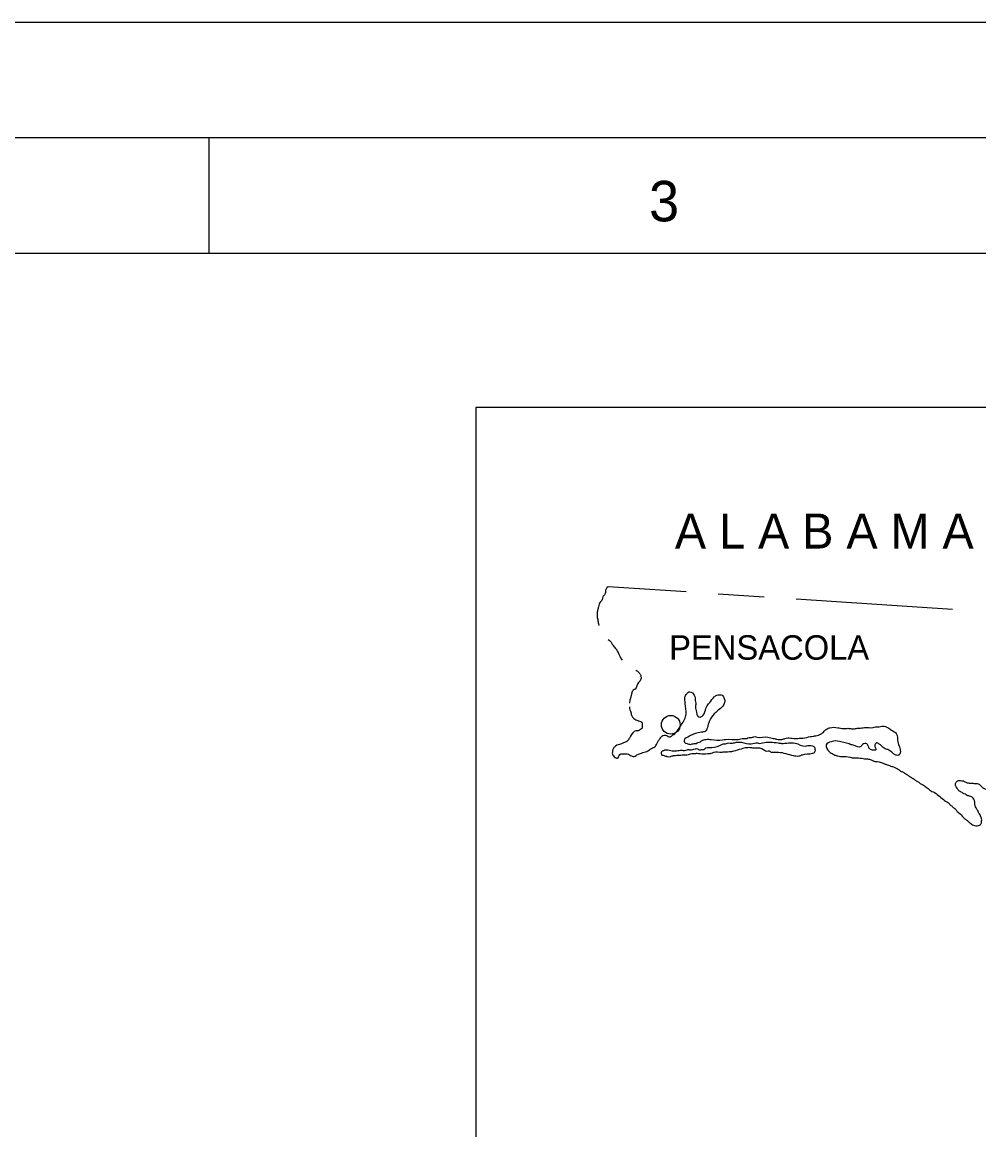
# Model space of a CAD drawing. Extents: x 384865 to 516869, y 1553900 to 1655899.
# Drawn here: x 469592 to 482007, y 1641531 to 1655899 of the extents above; entities that cross this region are included whole.
import ezdxf

# ---------------------------------------------------------------- set-up
doc = ezdxf.new("R2010")
doc.units = 0
for name, color, linetype in [('G-ANNO-NPLT', 7, 'Continuous'), ('G-ANNO-TTLB', 7, 'Continuous'), ('V-ANNO-SYMB', 7, 'Continuous')]:
    doc.layers.add(name, color=color, linetype=linetype)

msp = doc.modelspace()

# ---------------------------------------------------------------- linework, layer by layer
at = {"layer": 'G-ANNO-NPLT'}
msp.add_lwpolyline([(384865, 1655899), (516865, 1655899), (516865, 1553900), (384865, 1553900)], close=True, dxfattribs=at)
at = {"layer": 'G-ANNO-TTLB'}
msp.add_line((472015, 1654399), (472015, 1652899), dxfattribs=at)
for points in [[(386365, 1555400), (515365, 1555400), (515365, 1654399), (386365, 1654399)], [(513865, 1652899), (390115, 1652899), (390115, 1556900), (513865, 1556900)]]:
    msp.add_lwpolyline(points, close=True, dxfattribs=at)
at = {"layer": 'V-ANNO-SYMB'}
for p, q in [((505114, 1650899), (475479, 1650899)), ((475479, 1650899), (475479, 1624160)), ((478207, 1648508), (477195, 1648576)), ((479223, 1648440), (478622, 1648481)), ((481663, 1648281), (479636, 1648413))]:
    msp.add_line(p, q, dxfattribs=at)
msp.add_circle((478009, 1646785), 121, dxfattribs=at)
for points in [[(477195, 1648576), (477176, 1648557), (477164, 1648522), (477153, 1648479), (477128, 1648445), (477119, 1648411), (477107, 1648389), (477095, 1648377), (477072, 1648315), (477060, 1648271), (477054, 1648223), (477058, 1648164), (477069, 1648107), (477074, 1648086), (477082, 1648071)], [(477198, 1647891), (477234, 1647857), (477256, 1647823), (477288, 1647781), (477327, 1647721), (477343, 1647682), (477377, 1647622)], [(477554, 1647495), (477583, 1647475), (477611, 1647442), (477623, 1647401), (477613, 1647357), (477589, 1647332), (477548, 1647249), (477523, 1647234), (477502, 1647194), (477489, 1647140), (477476, 1647095), (477474, 1647064)], [(477472, 1647017), (477480, 1646979), (477491, 1646947), (477497, 1646920), (477513, 1646882), (477529, 1646866), (477556, 1646850), (477605, 1646833), (477632, 1646817), (477637, 1646779), (477637, 1646739), (477615, 1646723), (477588, 1646706), (477556, 1646706), (477488, 1646636), (477467, 1646601), (477429, 1646563), (477386, 1646547), (477370, 1646536), (477343, 1646531), (477278, 1646496), (477256, 1646463), (477251, 1646426), (477251, 1646404), (477289, 1646361), (477316, 1646350), (477348, 1646399), (477402, 1646409), (477424, 1646409), (477461, 1646404), (477488, 1646388), (477532, 1646374), (477559, 1646385), (477580, 1646401), (477602, 1646407), (477629, 1646418), (477699, 1646439), (477742, 1646469), (477802, 1646501), (477829, 1646539), (477845, 1646571), (477872, 1646609), (477904, 1646644), (477942, 1646650), (477969, 1646639), (477985, 1646628), (478018, 1646639), (478034, 1646655), (478050, 1646661), (478082, 1646693), (478169, 1646820), (478201, 1646890), (478201, 1647028), (478193, 1647136), (478199, 1647165), (478220, 1647192), (478231, 1647203), (478258, 1647214), (478290, 1647198), (478325, 1647133), (478325, 1647117), (478331, 1647084), (478331, 1647017), (478342, 1646947), (478385, 1646882), (478401, 1646887), (478428, 1646909), (478466, 1646998), (478498, 1647057), (478514, 1647074), (478574, 1647147), (478606, 1647168), (478644, 1647174), (478676, 1647168), (478703, 1647125), (478709, 1647103), (478698, 1647047), (478636, 1646982), (478501, 1646812), (478479, 1646731), (478463, 1646706), (478420, 1646690), (478388, 1646685), (478280, 1646652), (478253, 1646636), (478182, 1646585), (478188, 1646558), (478220, 1646542), (478263, 1646531), (478285, 1646536), (478339, 1646542)], [(478339, 1646542), (478361, 1646555), (478393, 1646566), (478409, 1646577), (478436, 1646588), (478501, 1646598), (478533, 1646593), (478682, 1646590), (478720, 1646596), (478882, 1646596), (478952, 1646607), (478995, 1646607), (479027, 1646620), (479060, 1646620), (479098, 1646631), (479130, 1646625), (479268, 1646625), (479306, 1646615), (479343, 1646609), (479381, 1646598), (479473, 1646601), (479489, 1646607), (479646, 1646607), (479700, 1646612), (479727, 1646612), (479821, 1646631), (479859, 1646636), (479875, 1646642), (479891, 1646642), (479962, 1646669), (479978, 1646679), (479999, 1646704), (480037, 1646731), (480075, 1646747), (480178, 1646747), (480248, 1646736), (480286, 1646736), (480307, 1646739), (480356, 1646733), (480383, 1646733), (480426, 1646739), (480453, 1646739), (480523, 1646750), (480634, 1646750), (480666, 1646758), (480693, 1646758), (480731, 1646763), (480796, 1646763), (480828, 1646747), (480872, 1646715), (480936, 1646671), (480955, 1646563), (480988, 1646431), (480971, 1646393), (480928, 1646393), (480826, 1646463), (480804, 1646469), (480755, 1646501), (480745, 1646512), (480715, 1646534), (480677, 1646550), (480661, 1646534), (480661, 1646493), (480669, 1646461), (480647, 1646455), (480612, 1646461), (480580, 1646488), (480575, 1646504), (480553, 1646536), (480499, 1646531), (480477, 1646504), (480375, 1646520), (480337, 1646531), (480310, 1646542), (480234, 1646558), (480199, 1646569), (480091, 1646566), (480026, 1646523), (480067, 1646436), (480116, 1646404), (480137, 1646393), (480175, 1646382), (480245, 1646372), (480283, 1646372), (480391, 1646355), (480445, 1646355), (480523, 1646345), (480561, 1646342), (480610, 1646331), (480642, 1646315), (480658, 1646310)], [(477972, 1646458), (478047, 1646447), (478085, 1646447), (478118, 1646453), (478155, 1646455), (478188, 1646450), (478220, 1646461), (478263, 1646461), (478325, 1646472), (478363, 1646472), (478379, 1646461), (478401, 1646461), (478423, 1646466), (478439, 1646466), (478466, 1646485), (478504, 1646490), (478644, 1646517), (478682, 1646534), (478703, 1646539), (478720, 1646539), (478747, 1646547), (478811, 1646547), (478860, 1646558), (478925, 1646558), (479054, 1646536), (479133, 1646550), (479165, 1646544), (479198, 1646550), (479403, 1646550), (479446, 1646544), (479624, 1646547), (479756, 1646509), (479789, 1646515), (479827, 1646515), (479864, 1646504), (479881, 1646455), (479870, 1646423), (479848, 1646412), (479713, 1646393), (479670, 1646377), (479632, 1646377), (479605, 1646382), (479408, 1646426), (479349, 1646426), (479306, 1646431), (479289, 1646442), (479257, 1646439), (479225, 1646450), (479203, 1646466), (479149, 1646482), (479084, 1646482), (479041, 1646488), (479009, 1646488), (478946, 1646477), (478747, 1646431), (478698, 1646431), (478671, 1646426), (478563, 1646426), (478531, 1646412), (478487, 1646407), (478385, 1646407), (478352, 1646412), (478304, 1646407), (478282, 1646407), (478217, 1646393), (478177, 1646393), (478139, 1646388), (478107, 1646388), (478069, 1646382), (478042, 1646382)], [(477907, 1646450), (477904, 1646447), (477891, 1646439), (477885, 1646426), (477885, 1646407), (477891, 1646393), (477910, 1646391), (477939, 1646380), (477953, 1646377), (477966, 1646372), (478001, 1646372), (478015, 1646377), (478042, 1646382)], [(477907, 1646450), (477920, 1646453), (477934, 1646458), (477947, 1646461), (477972, 1646458)], [(480658, 1646310), (480766, 1646288), (480799, 1646272), (480836, 1646261), (480877, 1646245), (480899, 1646239), (480936, 1646223), (480963, 1646207), (481001, 1646180), (481017, 1646175), (481050, 1646153), (481071, 1646142), (481109, 1646115), (481155, 1646088), (481177, 1646072), (481187, 1646061), (481220, 1646045), (481247, 1646023), (481279, 1646007), (481322, 1645975), (481349, 1645959), (481366, 1645942), (481433, 1645905), (481563, 1645802), (481601, 1645780), (481622, 1645764), (481633, 1645748), (481655, 1645732), (481665, 1645721), (481700, 1645694), (481727, 1645662), (481749, 1645645), (481803, 1645586), (481835, 1645559), (481852, 1645548), (481879, 1645521), (481925, 1645489), (481952, 1645478), (481984, 1645473), (482016, 1645483), (482033, 1645494), (482043, 1645537), (482043, 1645564), (482030, 1645602), (482014, 1645632), (482003, 1645648), (481992, 1645675), (481970, 1645707), (481960, 1645734), (481943, 1645821), (481887, 1645859), (481844, 1645875), (481833, 1645886), (481800, 1645896), (481779, 1645913), (481763, 1645918), (481736, 1645945), (481703, 1646015), (481719, 1646048), (481741, 1646061), (481768, 1646061), (481806, 1646056), (481827, 1646045), (481881, 1646029), (481919, 1646029), (481941, 1646023), (481984, 1646023), (482011, 1646013), (482049, 1645975), (482084, 1645953), (482116, 1645953), (482165, 1645975), (482278, 1646015), (482294, 1646015), (482327, 1646021), (482359, 1646021), (482402, 1646010), (482429, 1645994), (482467, 1646010), (482500, 1646034), (482532, 1646018), (482564, 1645967), (482570, 1645950), (482581, 1645940)]]:
    msp.add_spline(points, degree=3, dxfattribs=at)

# ---------------------------------------------------------------- texts
at = {"layer": 'G-ANNO-TTLB'}
msp.add_text('3', height=525, dxfattribs=at).set_placement((477727, 1653315))
at = {"layer": 'V-ANNO-SYMB'}
for s, height, p in [('A L A B A M A', 453.6, (478063, 1649071)), ('PENSACOLA', 317.5, (477988, 1647629))]:
    msp.add_text(s, height=height, rotation=0, dxfattribs=at).set_placement(p)

doc.saveas('drawing.dxf')
